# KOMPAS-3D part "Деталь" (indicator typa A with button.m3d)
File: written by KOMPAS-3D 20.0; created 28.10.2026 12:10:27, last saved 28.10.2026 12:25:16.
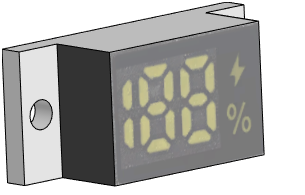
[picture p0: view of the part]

Document properties: Полное имя файла: D:\RicWork\Project-EPS32\box_compas\переключатели и кнопки\indicator typa A with button.m3d

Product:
- Part/product: Деталь
    Масса: 0.00511556

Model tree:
1. Эскиз:1
2. Элемент выдавливания:1
     Расстояние 1 = 1.5
3. Эскиз:2  (with: Элемент выдавливания:1)
4. Элемент выдавливания:2
     Расстояние 2 = 1.5
5. Эскиз:3  (with: Элемент выдавливания:1)
6. Элемент выдавливания:3
     Расстояние 1 = 4.6

Referenced files in D:\RicWork\Project-EPS32\box_compas\переключатели и кнопки\: indicator typa A with button bottom.png, indicator typa A with button up.png
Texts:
  indicator typa A with button bottom.png
  indicator typa A with button up.png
